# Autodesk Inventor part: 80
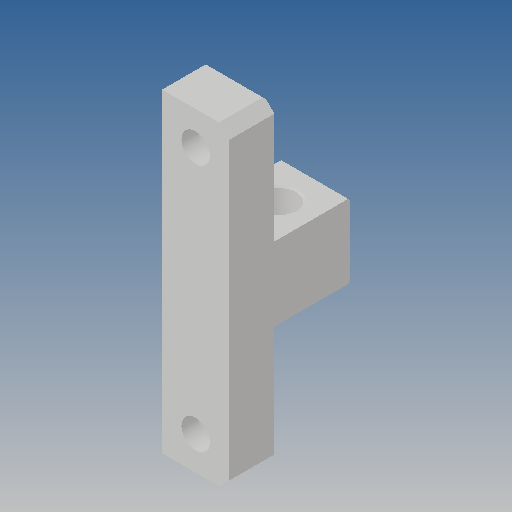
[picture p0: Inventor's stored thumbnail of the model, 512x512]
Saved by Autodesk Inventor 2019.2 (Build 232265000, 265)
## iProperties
Created: 2013-07
Part Number: 80
Material: Ogólny
Document SubType Name: Modeling
Designer: CADENGINEERING4
Density: 1 g/cm^3
Appearance: Domyślna
Author: CADENGINEERING4
Revision Number: ÈÎºÎ
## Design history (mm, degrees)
feature "CALC80-Ö§³Å×ù.bak-1-solid1"
node "Bryła1"
